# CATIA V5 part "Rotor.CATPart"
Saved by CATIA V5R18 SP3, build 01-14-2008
Part number: Rotor
Bounding box of the stored display mesh (mm): x -135 to 135, y -32.49 to 32.49, z 0 to 12
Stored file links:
  E:\#00 CATIA V5 Movie\#03 CATIA V5 Data\#07 KIN\Balance Unit (1)\Rotor.CATPart
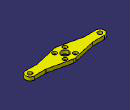
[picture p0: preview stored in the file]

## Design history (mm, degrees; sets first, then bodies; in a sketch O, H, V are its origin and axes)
Body1 (main body)
  Sketch1 on xy-plane, origin (0, 0, 0), H (1, 0, 0), V (0, 1, 0)
    point P1 (0, 33)
    line L1 (4.3902, 32.0122) -> (80, 15)
    point P2 (80, 15)
    line L2 (80, 15) -> (120, 15)
    point P3 (120, 15)
    arc A1 centre (120, 0) radius 15 from (120, 15) to (120, -15) cw
    point P4 (120, 0)
    point P5 (120, -15)
    line L3 (120, -15) -> (80, -15)
    point P6 (80, -15)
    line L4 (80, -15) -> (4.3902, -32.0122)
    point P7 (0, -33)
    point P8 (-80, 15)
    point P9 (-120, 15)
    point P11 (-120, -15)
    point P12 (-80, -15)
    line L5 (-80, 15) -> (-120, 15)
    arc A2 centre (-120, 0) radius 15 from (-120, 15) to (-120, -15) ccw
    line L6 (-120, -15) -> (-80, -15)
    line L7 (-4.3902, 32.0122) -> (-80, 15)
    line L8 (-80, -15) -> (-4.3902, -32.0122)
    axis line L9 (135, 0) -> (135, 45.6531)
    point P13 (135, 0)
    circle A3 centre (120, 0) radius 7
    point P15 (120, 0)
    circle A4 centre (0, 0) radius 13
    arc A5 centre (0, 12.5) radius 20 from (4.3902, 32.0122) to (-4.3902, 32.0122) ccw
    arc A6 centre (0, -12.5) radius 20 from (4.3902, -32.0122) to (-4.3902, -32.0122) cw
    circle A7 centre (-120, 0) radius 7
    distance A2 A1 = 270
    distance L9 P2 = 55
    distance P6 L9 = 55
    radius A3 = 7
    radius A4 = 13
    radius A5 = 20
    radius A6 = 20
    distance A6 A5 = 65
    distance V P15 = 120
    coincidence: P1 V, P7 V, P4 H, P13 A1, P13 H, P15 P4, L1 P1, L4 P7
    horizontal: L2 H, L3 H
    tangency: A1 L2, L3 A1, L9 A1, A5 L1, A5 L7, A6 L4, A6 L8
    symmetry: P2 P8 V, P3 P9 V, P5 P11 V, P6 P12 V, L2 L5 V, A1 A2 V, L3 L6 V, L1 L7 V, L4 L8 V, P7 P1 H, A3 A7 V
  Pad1: profile Sketch1, direction (0, 0, 1), length 12
  Sketch2 on end face of Pad1, origin (-17.7, 17.7, 12), H (1, 0, 0), V (0, 1, 0)
    point P1 (0, 0)
    reference projected point E1 (0, 0) from Sketch3.P4
    coincidence: E1 P1
  Hole1: placed by Sketch2, at (-17.7, 17.7, 12) direction (0, 0, -1), diameter 10, through (limit type 6), counterbore diameter 14, counterbore depth 8
  Sketch3 on end face of Pad1, origin (0, 0, 12), H (1, 0, 0), V (0, 1, 0)
    construction line L1 (17.7, 17.7) -> (17.7, -17.7)
    construction line L2 (17.7, -17.7) -> (-17.7, -17.7)
    construction line L3 (-17.7, -17.7) -> (-17.7, 17.7)
    construction line L4 (-17.7, 17.7) -> (17.7, 17.7)
    point P4 (-17.7, 17.7)
    distance L2 L4 = 35.4
    distance L1 L3 = 35.4
    vertical: L1 V, L3 V
    horizontal: L2 H, L4 H
    equidistance: L1 L3 O, L2 L4 O
  UserPattern1: of Hole1, copies 4, at the points of Sketch3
